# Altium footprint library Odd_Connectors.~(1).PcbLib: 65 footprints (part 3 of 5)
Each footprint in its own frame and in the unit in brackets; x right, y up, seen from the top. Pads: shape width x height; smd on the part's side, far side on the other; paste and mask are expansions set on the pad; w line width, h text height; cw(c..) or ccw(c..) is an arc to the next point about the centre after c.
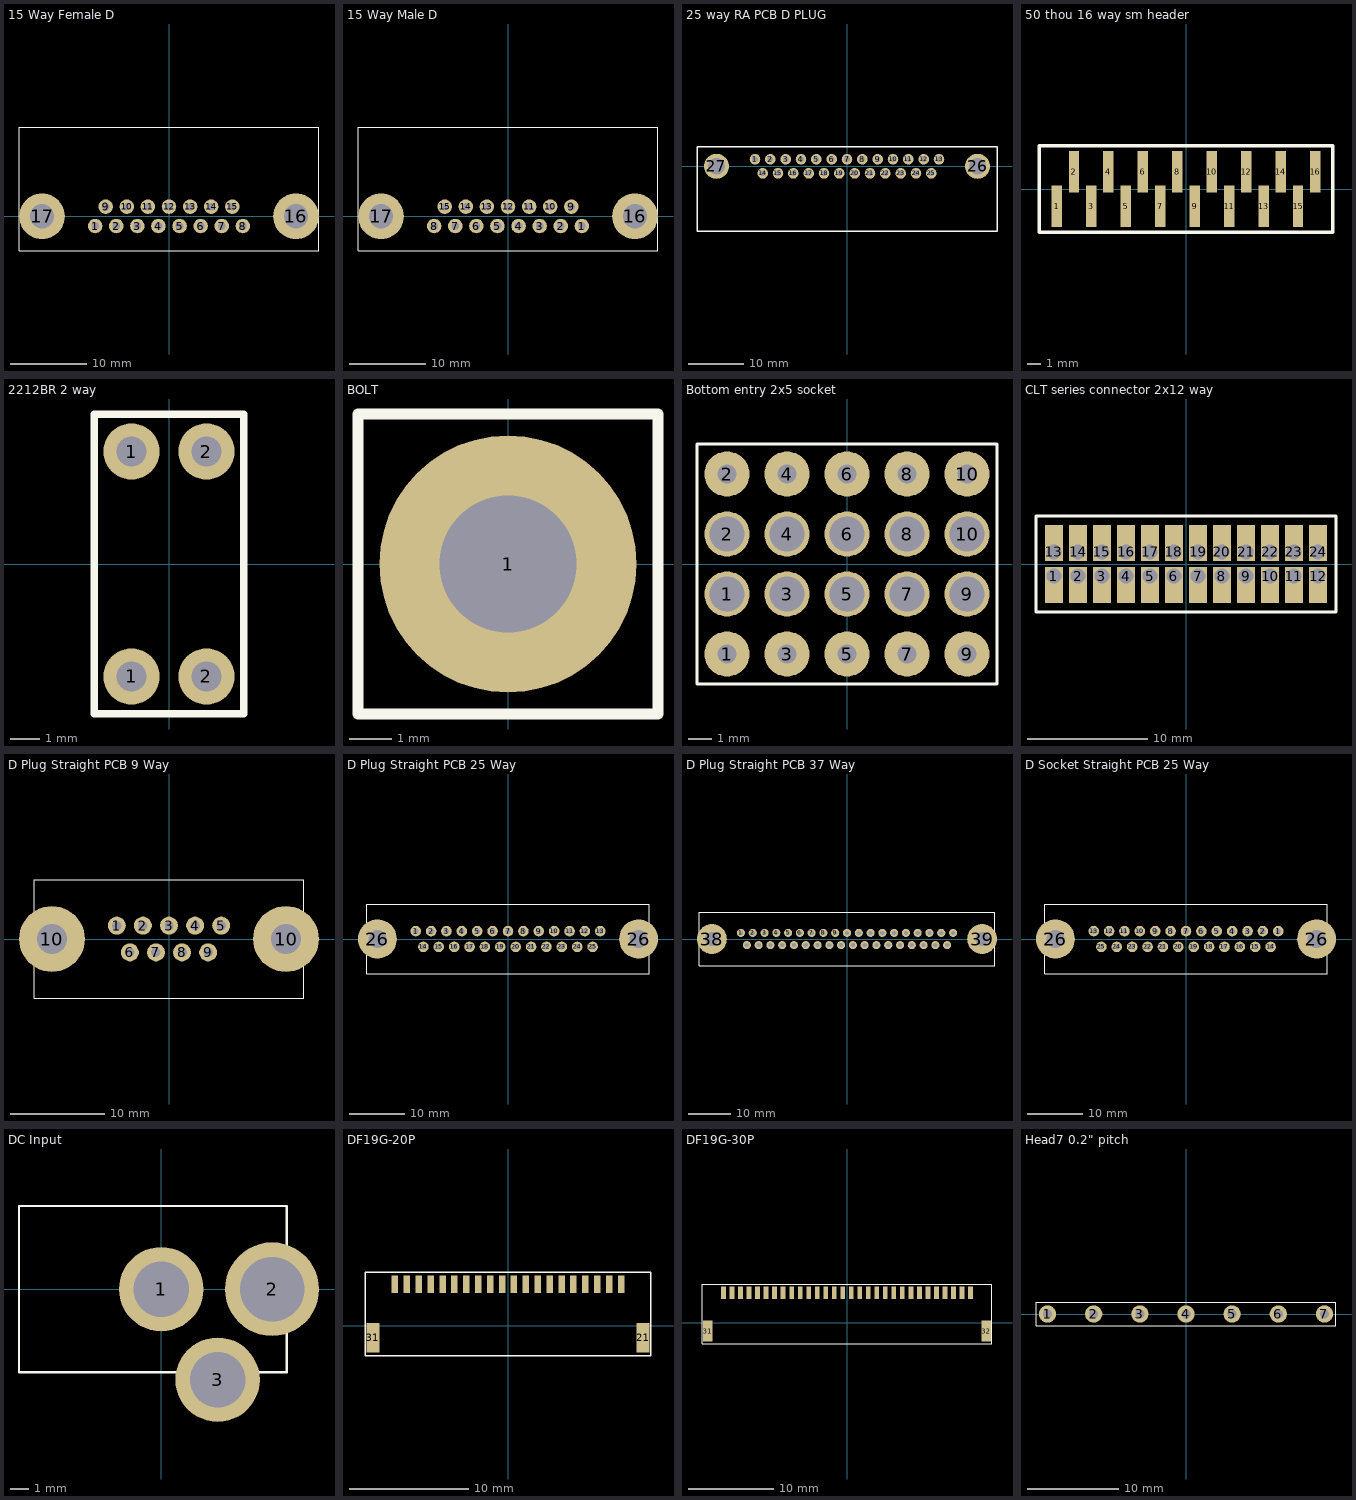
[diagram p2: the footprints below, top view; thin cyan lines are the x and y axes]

## 15 Way Female D [mm] "RA PCB mounted D connector"
height 11.5
pads (17):
  round 1.905 hole 1: 1(-9.69,-1.27) 2(-6.921,-1.27) 3(-4.153,-1.27) 4(-1.385,-1.27) 5(1.385,-1.27) 6(4.155,-1.27) 7(6.925,-1.27) 8(9.695,-1.27) 9(-8.306,1.275) 10(-5.537,1.275) 11(-2.769,1.275) 12(0,1.27) 13(2.77,1.27) 14(5.54,1.27) 15(8.31,1.27)
  round 6 hole 3.2: 16(16.66,0) 17(-16.66,0)
Top Overlay:
  lines w0.127: -19.685,-4.5 -19.685,11.675 19.685,11.675 19.685,-4.5 -19.685,-4.5

## 15 Way Male D [mm] "RA PCB mounted D connector"
height 11.5
pads (17):
  round 1.905 hole 1: 1(9.695,-1.27) 2(6.925,-1.27) 3(4.155,-1.27) 4(1.385,-1.27) 5(-1.385,-1.27) 6(-4.153,-1.27) 7(-6.921,-1.27) 8(-9.69,-1.27) 9(8.31,1.27) 10(5.54,1.27) 11(2.77,1.27) 12(0,1.27) 13(-2.769,1.275) 14(-5.537,1.275) 15(-8.306,1.275)
  round 6 hole 3.2: 16(16.66,0) 17(-16.66,0)
Top Overlay:
  lines w0.127: -19.685,-4.5 19.685,-4.5 19.685,11.675 -19.685,11.675 -19.685,-4.5

## 25 way RA PCB D PLUG [mm] "Harting data used"
height 12.5
pads (27):
  round 1.905 hole 1: 1(-16.56,1.27) 2(-13.8,1.27) 3(-11.04,1.27) 4(-8.28,1.27) 5(-5.52,1.27) 6(-2.76,1.27) 7(0,1.27) 8(2.76,1.27) 9(5.52,1.27) 10(8.28,1.27) 11(11.04,1.27) 12(13.8,1.27) 13(16.56,1.27) 14(-15.18,-1.27) 15(-12.42,-1.27) 16(-9.66,-1.27) 17(-6.9,-1.27) 18(-4.14,-1.27) 19(-1.38,-1.27) 20(1.38,-1.27) 21(4.14,-1.27) 22(6.9,-1.27) 23(9.66,-1.27) 24(12.42,-1.27) 25(15.18,-1.27)
  round 4.5 hole 3: 26(23.5,0) 27(-23.5,0)
Top Overlay:
  lines w0.254: -27,-11.67 -27,3.5 27,3.5 27,-11.67 -27,-11.67

## 50 thou 16 way sm header [mil] "50 thou 16 way sm header"
height 314.96
pads (16):
  rect 30x120 smd: 1(-375,-50) 2(-325,50) 3(-275,-50) 4(-225,50) 5(-175,-50) 6(-125,50) 7(-75,-50) 8(-25,50) 9(25,-50) 10(75,50) 11(125,-50) 12(175,50) 13(225,-50) 14(275,50) 15(325,-50) 16(375,50)
Top Overlay:
  lines w10: -425,-125 425,-125 425,125 -425,125 -425,-125

## 2212BR 2 way [mm] "0.1\" pitch PCB RA Sockets"
pads (4):
  round 1.905 hole 1: 1(-1.27,-3.81) 1(-1.27,3.81) 2(1.27,-3.81) 2(1.27,3.81)
Top Overlay:
  lines w0.254: -2.54,-5.08 2.54,-5.08 2.54,5.08 -2.54,5.08 -2.54,-5.08

## BOLT [mm] "M3 mounting bolt"
height 5
pads (1):
  round 6 hole 3.2: 1(0,0)
Top Overlay:
  lines w0.254: -3.5,-3.5 -3.5,3.5 3.5,3.5 3.5,-3.5 -3.5,-3.5

## Bottom entry 2x5 socket [mm] "Board to board connector, bottom entry, 2x5 way"
height 7
pads (20):
  round 1.905 hole 0.8: 1(-5.08,-3.81) 2(-5.08,3.81) 3(-2.54,-3.81) 4(-2.54,3.81) 5(0,-3.81) 6(0,3.81) 7(2.54,-3.81) 8(2.54,3.81) 9(5.08,-3.81) 10(5.08,3.81)
  round 1.905 hole 1.5: 1(-5.08,-1.27) 2(-5.08,1.27) 3(-2.54,-1.27) 4(-2.54,1.27) 5(0,-1.27) 6(0,1.27) 7(2.54,-1.27) 8(2.54,1.27) 9(5.08,-1.27) 10(5.08,1.27)
Top Overlay:
  lines w0.127: -6.35,-5.08 6.35,-5.08 6.35,5.08 -6.35,5.08 -6.35,-5.08

## CLT series connector 2x12 way [mm] "Samtec CLT low profile SM connector"
height 2.13
pads (24):
  rect 1.5x3 hole 1.22 copper offset 0,-0.75: 1(-11,-1) 2(-9,-1) 3(-7,-1) 4(-5,-1) 5(-3,-1) 6(-1,-1) 7(1,-1) 8(3,-1) 9(5,-1) 10(7,-1) 11(9,-1) 12(11,-1)
  rect 1.5x3 hole 1.22 copper offset 0,0.75: 13(-11,1) 14(-9,1) 15(-7,1) 16(-5,1) 17(-3,1) 18(-1,1) 19(1,1) 20(3,1) 21(5,1) 22(7,1) 23(9,1) 24(11,1)
Top Overlay:
  lines w0.254: -12.5,-4 -12.5,4 12.5,4 12.5,-4 -12.5,-4

## D Plug Straight PCB 9 Way [mil] "D Plug Straight PCB 9 Way"
height 472.44
pads (11):
  round 75 hole 39.37 unplated: 1(-218,56) 2(-109,56) 3(0,56) 4(109,56) 5(218,56) 6(-163.5,-56) 7(-54.5,-56) 8(54.5,-56) 9(163.5,-56)
  round 275.59 hole 125.98 unplated: 10(-489,0) 10(489,0)
Top Overlay:
  lines w1: -564,-247.05 -564,247.05 564,247.05 564,-247.05 -564,-247.05

## D Plug Straight PCB 25 Way [mil] "D Plug Straight PCB 25 Way"
height 472.44
pads (27):
  round 75 hole 39.37 unplated: 1(-654,56) 2(-545,56) 3(-436,56) 4(-327,56) 5(-218,56) 6(-109,56) 7(0,56) 8(109,56) 9(218,56) 10(327,56) 11(436,56) 12(545,56) 13(654,56) 14(-599.5,-56) 15(-490.5,-56) 16(-381.5,-56) 17(-272.5,-56) 18(-163.5,-56) 19(-54.5,-56) 20(54.5,-56) 21(163.5,-56) 22(272.5,-56) 23(381.5,-56) 24(490.5,-56) 25(599.5,-56)
  round 275.59 hole 125.98 unplated: 26(-925,0) 26(925,0)
Top Overlay:
  lines w1: -1000,-247.05 -1000,247.05 1000,247.05 1000,-247.05 -1000,-247.05

## D Plug Straight PCB 37 Way [mil] "D Plug Straight PCB 37 Way"
height 472.44
pads (39):
  round 75 hole 39.37: 1(-981,56) 2(-872,56) 3(-763,56) 4(-654,56) 5(-545,56) 6(-436,56) 7(-327,56) 8(-218,56) 9(-109,56) 10(0,56) 11(109,56) 12(218,56) 13(327,56) 14(436,56) 15(545,56) 16(654,56) 17(763,56) 18(872,56) 19(981,56) 20(-926.5,-56) 21(-817.5,-56) 22(-708.5,-56) 23(-599.5,-56) 24(-490.5,-56) 25(-381.5,-56) 26(-272.5,-56) 27(-163.5,-56) 28(-54.5,-56) 29(54.5,-56) 30(163.5,-56) 31(272.5,-56) 32(381.5,-56) 33(490.5,-56) 34(599.5,-56) 35(708.5,-56) 36(817.5,-56) 37(926.5,-56)
  round 275.59 hole 125.98: 38(-1250,0) 39(1250,0)
Top Overlay:
  lines w10: -1365,-247.05 -1365,247.05 1365,247.05 1365,-247.05 -1365,-247.05

## D Socket Straight PCB 25 Way [mil] "D socket Straight PCB 25 Way"
height 472.44
pads (27):
  round 75 hole 39.37 unplated: 1(654,56) 2(545,56) 3(436,56) 4(327,56) 5(218,56) 6(109,56) 7(0,56) 8(-109,56) 9(-218,56) 10(-327,56) 11(-436,56) 12(-545,56) 13(-654,56) 14(599.5,-56) 15(490.5,-56) 16(381.5,-56) 17(272.5,-56) 18(163.5,-56) 19(54.5,-56) 20(-54.5,-56) 21(-163.5,-56) 22(-272.5,-56) 23(-381.5,-56) 24(-490.5,-56) 25(-599.5,-56)
  round 275.59 hole 125.98 unplated: 26(-925,0) 26(925,0)
Top Overlay:
  lines w1: -1000,-247.05 -1000,247.05 1000,247.05 1000,-247.05 -1000,-247.05

## DC Input [mm] "DC Power input, 2.1 or 2.5mm pin"
height 11
pads (3):
  round 4.572 hole 3: 1(0,0) 3(3.05,-4.9)
  round 5.08 hole 3.5: 2(6,0)
Top Overlay:
  lines w0.127: -7.7,-4.5 6.8,-4.5 6.8,4.5 -7.7,4.5 -7.7,-4.5

## DF19G-20P [mm] "Hirose 1mm pitch connector"
height 1.6
pads (22):
  rect 0.55x1.5 smd: 1(-9.5,3.5) 2(-8.5,3.5) 3(-7.5,3.5) 4(-6.5,3.5) 5(-5.5,3.5) 6(-4.5,3.5) 7(-3.5,3.5) 8(-2.5,3.5) 9(-1.5,3.5) 10(-0.5,3.5) 11(0.5,3.5) 12(1.5,3.5) 13(2.5,3.5) 14(3.5,3.5) 15(4.5,3.5) 16(5.5,3.5) 17(6.5,3.5) 18(7.5,3.5) 19(8.5,3.5) 20(9.5,3.5)
  rect 1.1x2.5 smd: 21(11.35,-1) 31(-11.35,-1)
Top Overlay:
  lines w0.127: -12,-2.5 12,-2.5 12,4.5 -12,4.5 -12,-2.5

## DF19G-30P [mm] "Hirose 1mm pitch connector"
height 1.6
pads (32):
  rect 0.55x1.5 smd: 1(-14.5,3.5) 2(-13.5,3.5) 3(-12.5,3.5) 4(-11.5,3.5) 5(-10.5,3.5) 6(-9.5,3.5) 7(-8.5,3.5) 8(-7.5,3.5) 9(-6.5,3.5) 10(-5.5,3.5) 11(-4.5,3.5) 12(-3.5,3.5) 13(-2.5,3.5) 14(-1.5,3.5) 15(-0.5,3.5) 16(0.5,3.5) 17(1.5,3.5) 18(2.5,3.5) 19(3.5,3.5) 20(4.5,3.5) 21(5.5,3.5) 22(6.5,3.5) 23(7.5,3.5) 24(8.5,3.5) 25(9.5,3.5) 26(10.5,3.5) 27(11.5,3.5) 28(12.5,3.5) 29(13.5,3.5) 30(14.5,3.5)
  rect 1.1x2.5 smd: 31(-16.35,-1) 32(16.35,-1)
Top Overlay:
  lines w0.127: -17,-2.5 17,-2.5 17,4.5 -17,4.5 -17,-2.5

## Head7 0.2" pitch [mm] "7 way header on 0.2\" pitch"
height 12.7
pads (7):
  round 1.905 hole 1: 1(-15.24,0) 2(-10.16,0) 3(-5.08,0) 4(0,0) 5(5.08,0) 6(10.16,0) 7(15.24,0)
Top Overlay:
  lines w0.127: -16.51,-1.27 -16.51,1.27 16.51,1.27 16.51,-1.27 -16.51,-1.27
